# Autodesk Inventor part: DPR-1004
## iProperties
Created: 2004-11
Part Number: DPR-1004
Cost Center: 0 lbmass
Document SubType Name: Modeling
Designer: busseym
Manufacturer: Standard
Standards Organization: Custom
Stock Number: DPR-1004
Density: 1 g/cm^3
CAGE: 1LJX3
Dept. ID: Product Design
Description #2: ---
Finish #1: ---
Finish #2: ---
Material ID: ---
Project Number: ---
Author: busseym
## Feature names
1. Revolution1
2. Extrusion1
3. Extrusion2
